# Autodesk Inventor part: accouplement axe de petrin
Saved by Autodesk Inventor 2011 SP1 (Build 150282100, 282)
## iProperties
Created: 2010-12
Part Number: accouplement axe de petrin
Document SubType Name: Modeling
Designer: eric
Density: 1 g/cm^3
Mass: 0.655249 g
Surface Area: 14.5672 cm^2
Volume: 0.655249 cm^3
Author: eric
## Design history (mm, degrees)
feature "Base1"
node "Solide1"
node "Corps solides"
node "Corps surfaciques"
